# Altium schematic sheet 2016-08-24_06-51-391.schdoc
size 287 x 165 mm; SheetNumber: 1; SheetTotal: 1
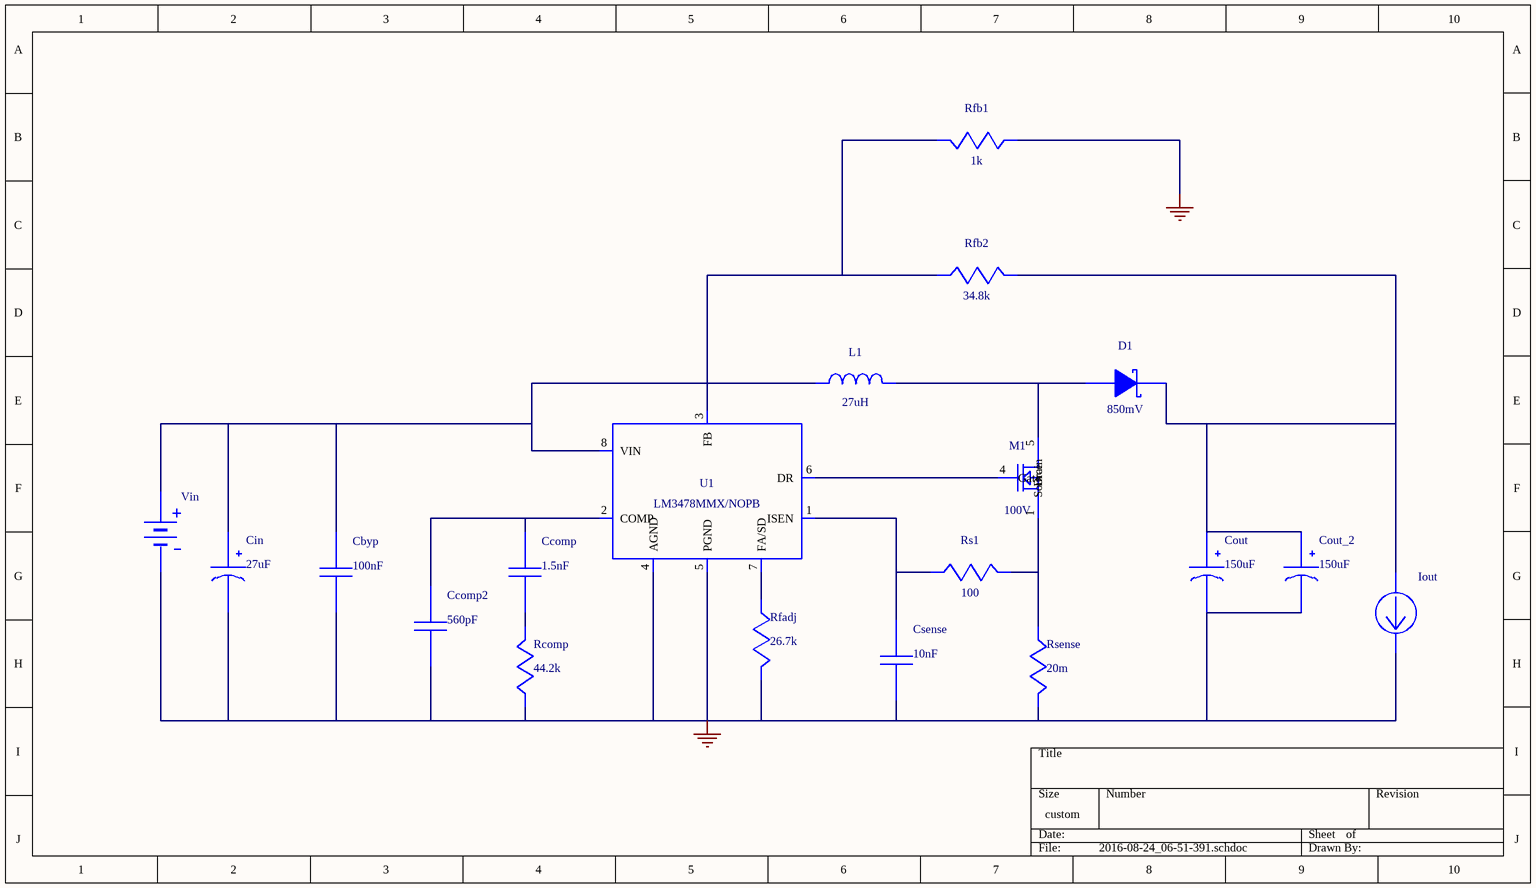
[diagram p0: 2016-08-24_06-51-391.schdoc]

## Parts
Cbyp  value 100nF  (hidden comment: 08053C104KAT2A)
Ccomp  value 1.5nF  (hidden comment: CC0805KRX7R9BB152)
Ccomp2  value 560pF  (hidden comment: CL21C561JBANFNC)
Cin  value 27uF  (hidden comment: UUD1V270MCL1GS)
Cout  value 150uF  (hidden comment: EEV-FK2A151M)
Cout_2  value 150uF  (hidden comment: EEV-FK2A151M)
Csense  value 10nF  (hidden comment: GRM216R71H103KA01D)
D1  value 850mV  (hidden comment: SK310A-TP)
Iout  WB_CURRENT_LOAD  (value not drawn)
L1  value 27uH  (hidden comment: SRR1210-270M)
M1  value 100V  (hidden comment: CSD19537Q3)
Rcomp  value 44.2k  (hidden comment: CRCW040244K2FKED)
Rfadj  value 26.7k  (hidden comment: CRCW040226K7FKED)
Rfb1  value 1k  (hidden comment: CRCW04021K00FKED)
Rfb2  value 34.8k  (hidden comment: CRCW040234K8FKED)
Rs1  value 100  (hidden comment: CRCW0402100RFKED)
Rsense  value 20m  (hidden comment: CSR1206FK20L0)
U1  LM3478MM/NOPB  (value not drawn)
Vin  WB_BATTERY  (value not drawn)

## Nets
0: Cbyp.2 Ccomp2.2 Cin.2(-) Cout.2(-) Cout_2.2(-) Csense.2 Iout.2(-) Rcomp.2 Rfadj.1 Rfb1.2 Rsense.1 U1.4(AGND) U1.5(PGND) Vin.2(-)
NetCbyp_1: Cbyp.1 Cin.1(+) L1.1 U1.8(VIN) Vin.1(+)
NetCcomp_1: Ccomp.1 Ccomp2.1 U1.2(COMP)
NetCcomp_2: Ccomp.2 Rcomp.1
NetCout_1: Cout.1(+) Cout_2.1(+) D1.1(K) Iout.1(+) Rfb2.1
NetCsense_1: Csense.1 Rs1.2 U1.1(ISEN)
NetD1_2: D1.2(A) L1.2 M1.5(Drain) M1.6(Drain) M1.7(Drain) M1.8(Drain) M1.9(Drain)
NetM1_1: M1.1(Source) M1.2(Source) M1.3(Source) Rs1.1 Rsense.2
NetM1_4: M1.4(Gate) U1.6(DR)
NetRfadj_2: Rfadj.2 U1.7(FA/SD)
NetRfb1_1: Rfb1.1 Rfb2.2 U1.3(FB)

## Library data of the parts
Cbyp = 08053C104KAT2A: Manufacturer Name: AVX
Ccomp = CC0805KRX7R9BB152: CC0805KRX7R9BB15; Manufacturer Name: Yageo America
Ccomp2 = CL21C561JBANFNC: Manufacturer Name: Samsung Electro-Mechanics
Cin = UUD1V270MCL1GS: Manufacturer Name: Nichicon
Cout Cout_2 = EEV-FK2A151M: Manufacturer Name: Panasonic
Csense = GRM216R71H103KA01D: GRM216R71H103KA0; Manufacturer Name: MuRata
D1 = SK310A-TP: Manufacturer Name: Micro Commercial Components
L1 = SRR1210-270M: Manufacturer Name: Bourns
M1 = CSD19537Q3: Manufacturer Name: Texas Instruments
Rcomp = CRCW040244K2FKED: Manufacturer Name: Vishay-Dale
Rfadj = CRCW040226K7FKED: Manufacturer Name: Vishay-Dale
Rfb1 = CRCW04021K00FKED: Manufacturer Name: Vishay-Dale
Rfb2 = CRCW040234K8FKED: Manufacturer Name: Vishay-Dale
Rs1 = CRCW0402100RFKED: Manufacturer Name: Vishay-Dale
Rsense = CSR1206FK20L0: Manufacturer Name: Stackpole Electronics Inc
U1 = LM3478MM/NOPB: LM3478MMX/NOPB; Manufacturer Name: Texas Instruments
